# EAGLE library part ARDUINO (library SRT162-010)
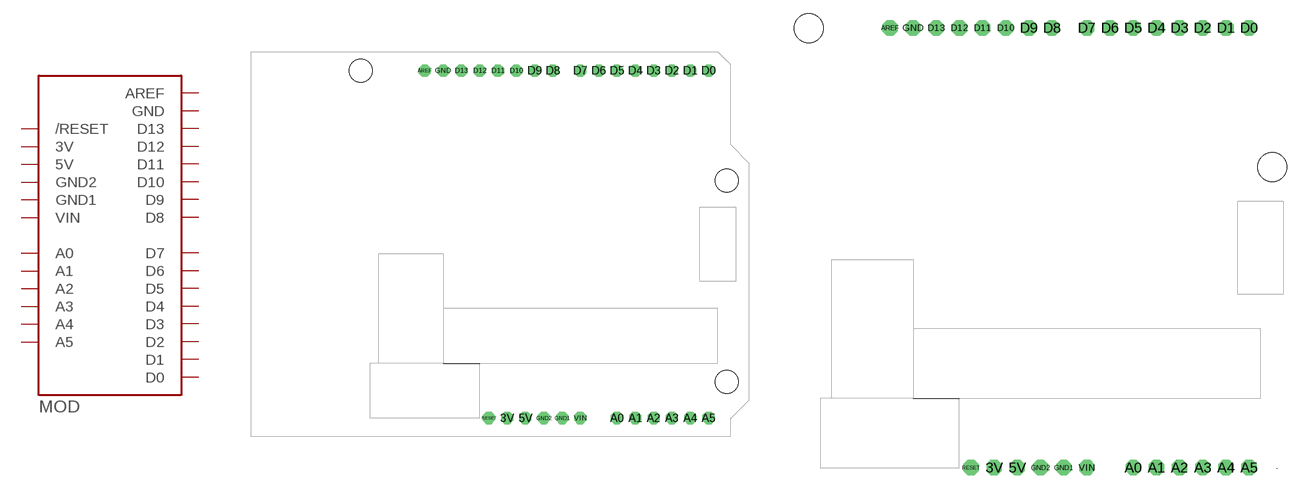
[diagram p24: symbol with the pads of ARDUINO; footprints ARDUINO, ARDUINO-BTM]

Designator prefix MOD

## ARDUINO  [ARDUINO]
3V  3V  pwr
5V  5V  pwr
A0  A0
A1  A1
A2  A2
A3  A3
A4  A4
A5  A5
AREF  AREF
D0  D0
D1  D1
D2  D2
D3  D3
D4  D4
D5  D5
D6  D6
D7  D7
D8  D8
D9  D9
D10  D10
D11  D11
D12  D12
D13  D13
GND  GND  pwr
GND1  GND1  pwr
GND2  GND2  pwr
RESET  /RESET
VIN  VIN  pwr

## ARDUINOBTM  [ARDUINO-BTM]
Pads as for ARDUINO

## Footprint ARDUINO (pad centres in mm)
drill 1 pad 1.676 octagon: 3V 0,-22.86; 5V 2.54,-22.86; A0 15.24,-22.86; A1 17.78,-22.86; A2 20.32,-22.86; A3 22.86,-22.86; A4 25.4,-22.86; A5 27.94,-22.86; AREF -11.43,25.4; D0 27.94,25.4; D1 25.4,25.4; D2 22.86,25.4; D3 20.32,25.4; D4 17.78,25.4; D5 15.24,25.4; D6 12.7,25.4; D7 10.16,25.4; D8 6.35,25.4; D9 3.81,25.4; D10 1.27,25.4; D11 -1.27,25.4; D12 -3.81,25.4; D13 -6.35,25.4; GND -8.89,25.4; GND1 7.62,-22.86; GND2 5.08,-22.86; RESET -2.54,-22.86; VIN 10.16,-22.86
hole 3.2 at -20.32,25.354
hole 3.2 at 30.48,10.114
hole 3.2 at 30.48,-17.826

## Footprint ARDUINO-BTM (pad centres in mm)
drill 1 pad 1.676 octagon: 3V 2.54,-22.86; 5V 5.08,-22.86; A0 17.78,-22.86; A1 20.32,-22.86; A2 22.86,-22.86; A3 25.4,-22.86; A4 27.94,-22.86; A5 30.48,-22.86; AREF -8.89,25.4; D0 30.48,25.4; D1 27.94,25.4; D2 25.4,25.4; D3 22.86,25.4; D4 20.32,25.4; D5 17.78,25.4; D6 15.24,25.4; D7 12.7,25.4; D8 8.89,25.4; D9 6.35,25.4; D10 3.81,25.4; D11 1.27,25.4; D12 -1.27,25.4; D13 -3.81,25.4; GND -6.35,25.4; GND1 10.16,-22.86; GND2 7.62,-22.86; RESET 0,-22.86; VIN 12.7,-22.86
hole 3.2 at -17.78,25.354
hole 3.2 at 33.02,10.114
